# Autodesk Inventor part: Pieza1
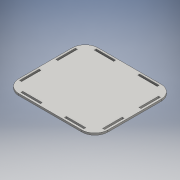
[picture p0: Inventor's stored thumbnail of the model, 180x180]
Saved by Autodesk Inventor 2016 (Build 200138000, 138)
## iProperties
Created: 2016-06
Part Number: Pieza1
Material: Genérico
Document SubType Name: Modeling
Designer: adm
Density: 1 g/cm^3
Appearance: Valor por defecto
Author: adm
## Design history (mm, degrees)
sketch "Boceto1"
  geometry: L1 (68.5, -61)-(-68.5, -61); L2 (-68.5, -61)-(-68.5, 61); L3 (-68.5, 61)-(68.5, 61); L4 (68.5, 61)-(68.5, -61); L5 (48.5, 58)-(48.5, 55); L6 (48.5, -55)-(48.5, -58); L7 (18.5, 58)-(18.5, 55); L8 (18.5, -55)-(18.5, -58); L9 (-18.5, 58)-(-18.5, 55); L10 (-18.5, -55)-(-18.5, -58); L11 (-48.5, 58)-(-48.5, 55); L12 (-48.5, -55)-(-48.5, -58); L13 (-65.5, 43)-(-62.5, 43); L14 (62.5, 43)-(65.5, 43); L15 (-65.5, 13)-(-62.5, 13); L16 (62.5, 13)-(65.5, 13); L17 (-65.5, -13)-(-62.5, -13); L18 (62.5, -13)-(65.5, -13); L19 (-65.5, -43)-(-62.5, -43); L20 (62.5, -43)-(65.5, -43); L21 (48.5, 58)-(18.5, 58); L22 (-18.5, 58)-(-48.5, 58); L23 (-48.5, 55)-(-18.5, 55); L24 (18.5, 55)-(48.5, 55); L25 (-62.5, -43)-(-62.5, -13); L26 (-62.5, 13)-(-62.5, 43); L27 (-65.5, 43)-(-65.5, 13); L28 (-65.5, -13)-(-65.5, -43); L29 (48.5, -55)-(18.5, -55); L30 (-18.5, -55)-(-48.5, -55); L31 (-48.5, -58)-(-18.5, -58); L32 (18.5, -58)-(48.5, -58); L33 (65.5, -43)-(65.5, -13); L34 (65.5, 13)-(65.5, 43); L35 (62.5, 43)-(62.5, 13); L36 (62.5, -13)-(62.5, -43); 1 further point
  constraints: 72 end point, 18 parallel, 11 horizontal, 11 perpendicular, 6 vertical
  dimensions: "d4" = 137 distance of L2.end L3.end; "d5" = 122 distance of L1.end L2.end; "d15" = 37 distance between parallel lines of L7 L9
extrude "Extrusión1" new body sketch "Boceto1" distance "d16" = 3; taper "d17" = 0 deg
fillet "Empalme1" dims "d21" = 20
node "Sólido1"
other parameters: "d3" = 3, "d12" = 18, "d14" = 18
